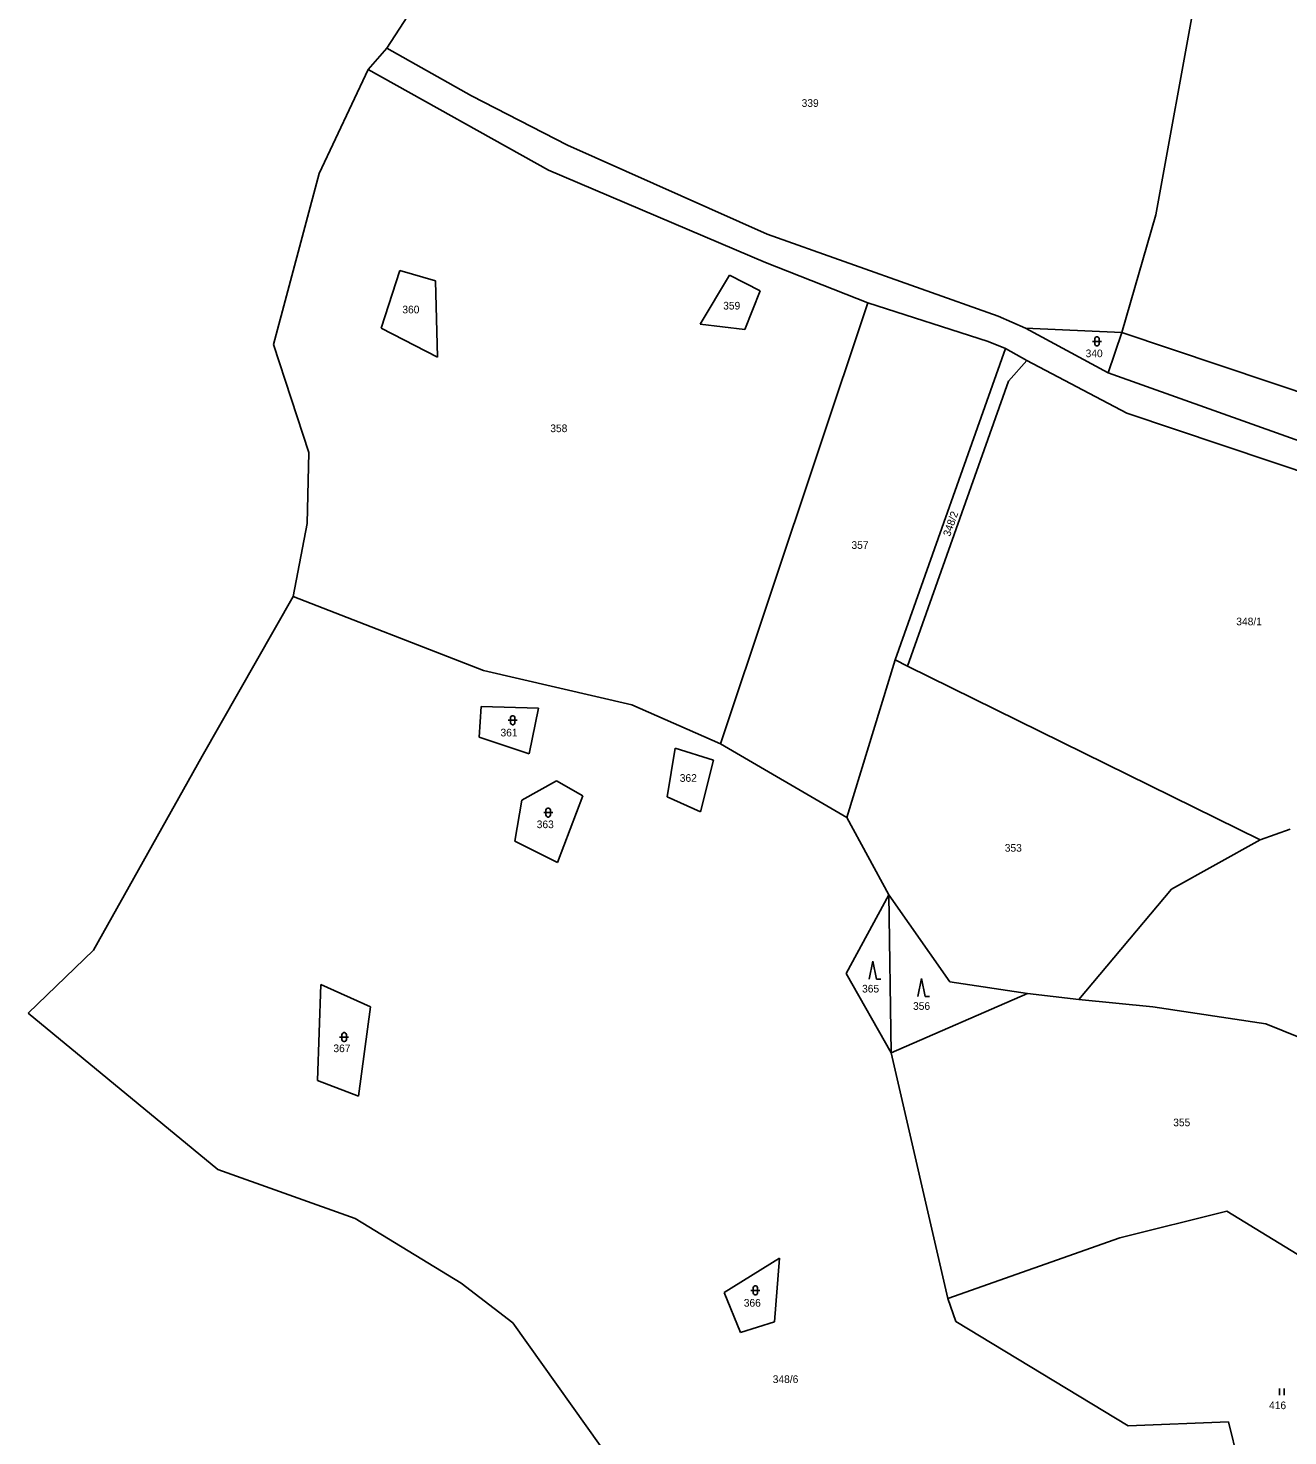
# Model space of a CAD drawing. Extents: x -794421 to -792735, y -1117671 to -1115559.
# Drawn here: x -794420.7 to -794140.7, y -1117103.6 to -1116790.7 of the extents above; entities that cross this region are included whole.
import ezdxf

# ---------------------------------------------------------------- set-up
doc = ezdxf.new("R2010")
doc.units = 0
for name, color, linetype in [('Vrstva 1', 7, 'Continuous'), ('Vrstva 14', 7, 'Continuous'), ('Vrstva 23', 7, 'Continuous'), ('Vrstva 4', 7, 'Continuous')]:
    doc.layers.add(name, color=color, linetype=linetype)

msp = doc.modelspace()

# ---------------------------------------------------------------- linework, layer by layer
at = {"layer": 'Vrstva 1'}
for p, q in [((-794161.02, -1116782.51), (-794170.01, -1116832.22)), ((-794340.93, -1116795.12), (-794322.16, -1116805.77)), ((-794345.11, -1116799.88), (-794305, -1116822.28)), ((-794322.16, -1116805.77), (-794300.83, -1116816.69)), ((-794300.83, -1116816.69), (-794256.39, -1116836.48)), ((-794305, -1116822.28), (-794256.82, -1116842.78)), ((-794170.01, -1116832.22), (-794177.62, -1116858.32)), ((-794256.39, -1116836.48), (-794205.08, -1116854.73)), ((-794342.23, -1116857.41), (-794338.11, -1116844.55)), ((-794338.11, -1116844.55), (-794330.16, -1116846.87)), ((-794256.82, -1116842.78), (-794234.07, -1116851.75)), ((-794330.16, -1116846.87), (-794329.71, -1116863.85)), ((-794271.32, -1116856.49), (-794264.82, -1116845.62)), ((-794264.82, -1116845.62), (-794257.96, -1116849.1)), ((-794257.96, -1116849.1), (-794261.38, -1116857.68)), ((-794266.82, -1116949.75), (-794234.07, -1116851.75)), ((-794234.07, -1116851.75), (-794207.31, -1116860.32)), ((-794205.08, -1116854.73), (-794199.03, -1116857.38)), ((-794329.71, -1116863.85), (-794342.23, -1116857.41)), ((-794261.38, -1116857.68), (-794271.32, -1116856.49)), ((-794199.03, -1116857.38), (-794177.62, -1116858.32)), ((-794180.61, -1116867.3), (-794199.03, -1116857.38)), ((-794207.31, -1116860.32), (-794203.46, -1116861.91)), ((-794177.62, -1116858.32), (-794180.61, -1116867.3)), ((-794177.62, -1116858.32), (-794117.35, -1116878.62)), ((-794203.46, -1116861.91), (-794228, -1116931.14)), ((-794203.46, -1116861.91), (-794198.74, -1116864.57)), ((-794198.74, -1116864.57), (-794202.79, -1116869.2)), ((-794198.74, -1116864.57), (-794176.47, -1116876.29)), ((-794202.79, -1116869.2), (-794225.24, -1116932.5)), ((-794180.61, -1116867.3), (-794121.37, -1116888.44)), ((-794176.47, -1116876.29), (-794087.13, -1116906.27)), ((-794361.8, -1116917.06), (-794319.51, -1116933.5)), ((-794228, -1116931.14), (-794238.71, -1116966.15)), ((-794228, -1116931.14), (-794225.24, -1116932.5)), ((-794225.24, -1116932.5), (-794146.84, -1116971.14)), ((-794319.51, -1116933.5), (-794286.54, -1116941.11)), ((-794320.44, -1116948.27), (-794320.03, -1116941.5)), ((-794320.03, -1116941.5), (-794307.28, -1116941.84)), ((-794307.28, -1116941.84), (-794309.35, -1116952.01)), ((-794286.54, -1116941.11), (-794266.82, -1116949.75)), ((-794309.35, -1116952.01), (-794320.44, -1116948.27)), ((-794278.69, -1116961.59), (-794276.9, -1116950.76)), ((-794276.9, -1116950.76), (-794268.37, -1116953.42)), ((-794238.71, -1116966.15), (-794266.82, -1116949.75)), ((-794268.37, -1116953.42), (-794271.28, -1116964.86)), ((-794310.99, -1116962.29), (-794303.23, -1116957.97)), ((-794303.23, -1116957.97), (-794297.42, -1116961.34)), ((-794312.52, -1116971.45), (-794310.99, -1116962.29)), ((-794297.42, -1116961.34), (-794303.06, -1116976.14)), ((-794271.28, -1116964.86), (-794278.69, -1116961.59)), ((-794238.71, -1116966.15), (-794229.41, -1116983.37)), ((-794146.84, -1116971.14), (-794140.21, -1116968.76)), ((-794303.06, -1116976.14), (-794312.52, -1116971.45)), ((-794166.58, -1116982.11), (-794146.84, -1116971.14)), ((-794187.16, -1117006.64), (-794166.58, -1116982.11)), ((-794238.83, -1117000.84), (-794229.41, -1116983.37)), ((-794229.41, -1116983.37), (-794215.84, -1117002.69)), ((-794229.41, -1116983.37), (-794228.89, -1117018.46)), ((-794228.89, -1117018.46), (-794238.83, -1117000.84)), ((-794355.63, -1117003.25), (-794356.35, -1117024.63)), ((-794355.63, -1117003.25), (-794344.61, -1117008.25)), ((-794215.84, -1117002.69), (-794198.58, -1117005.26)), ((-794198.58, -1117005.26), (-794228.89, -1117018.46)), ((-794187.16, -1117006.64), (-794198.58, -1117005.26)), ((-794187.16, -1117006.64), (-794170.7, -1117008.24)), ((-794344.61, -1117008.25), (-794347.26, -1117028.13)), ((-794170.7, -1117008.24), (-794145.61, -1117012.04)), ((-794145.61, -1117012.04), (-794118.17, -1117023.08)), ((-794228.89, -1117018.46), (-794216.26, -1117073.1)), ((-794347.26, -1117028.13), (-794356.35, -1117024.63)), ((-794178.01, -1117059.58), (-794154.29, -1117053.65)), ((-794154.29, -1117053.65), (-794132.18, -1117067.16)), ((-794216.26, -1117073.1), (-794178.01, -1117059.58)), ((-794266.02, -1117071.76), (-794253.72, -1117064.08)), ((-794253.72, -1117064.08), (-794254.77, -1117078.24)), ((-794262.35, -1117080.65), (-794266.02, -1117071.76)), ((-794214.5, -1117078.17), (-794216.26, -1117073.1)), ((-794254.77, -1117078.24), (-794262.35, -1117080.65)), ((-794176.15, -1117101.34), (-794214.5, -1117078.17)), ((-794153.88, -1117100.48), (-794176.15, -1117101.34)), ((-794151.74, -1117109.25), (-794153.88, -1117100.48))]:
    msp.add_line(p, q, dxfattribs=at)
at = {"layer": 'Vrstva 23'}
for p, q in [((-794184.13, -1116860.32), (-794182.13, -1116860.32)), ((-794183.63, -1116859.72), (-794183.53, -1116859.52)), ((-794183.63, -1116860.92), (-794183.63, -1116859.72)), ((-794183.53, -1116861.12), (-794183.63, -1116860.92)), ((-794183.53, -1116859.52), (-794183.43, -1116859.42)), ((-794183.43, -1116859.42), (-794183.23, -1116859.32)), ((-794183.23, -1116859.32), (-794183.03, -1116859.32)), ((-794183.03, -1116859.32), (-794182.83, -1116859.42)), ((-794182.83, -1116859.42), (-794182.73, -1116859.52)), ((-794182.73, -1116859.52), (-794182.63, -1116859.72)), ((-794182.63, -1116860.92), (-794182.73, -1116861.12)), ((-794182.63, -1116859.72), (-794182.63, -1116860.92)), ((-794183.43, -1116861.22), (-794183.53, -1116861.12)), ((-794183.23, -1116861.32), (-794183.43, -1116861.22)), ((-794183.03, -1116861.32), (-794183.23, -1116861.32)), ((-794182.83, -1116861.22), (-794183.03, -1116861.32)), ((-794182.73, -1116861.12), (-794182.83, -1116861.22)), ((-794313.99, -1116944.54), (-794311.99, -1116944.54)), ((-794313.49, -1116943.94), (-794313.39, -1116943.74)), ((-794313.49, -1116945.14), (-794313.49, -1116943.94)), ((-794313.39, -1116945.34), (-794313.49, -1116945.14)), ((-794313.39, -1116943.74), (-794313.29, -1116943.64)), ((-794313.29, -1116945.44), (-794313.39, -1116945.34)), ((-794313.29, -1116943.64), (-794313.09, -1116943.54)), ((-794313.09, -1116945.54), (-794313.29, -1116945.44)), ((-794313.09, -1116943.54), (-794312.89, -1116943.54)), ((-794312.89, -1116943.54), (-794312.69, -1116943.64)), ((-794312.69, -1116945.44), (-794312.89, -1116945.54)), ((-794312.69, -1116943.64), (-794312.59, -1116943.74)), ((-794312.59, -1116945.34), (-794312.69, -1116945.44)), ((-794312.59, -1116943.74), (-794312.49, -1116943.94)), ((-794312.49, -1116945.14), (-794312.59, -1116945.34)), ((-794312.49, -1116943.94), (-794312.49, -1116945.14)), ((-794312.89, -1116945.54), (-794313.09, -1116945.54)), ((-794305.5, -1116964.25), (-794305.4, -1116964.15)), ((-794305.4, -1116964.15), (-794305.2, -1116964.05)), ((-794305.2, -1116964.05), (-794305, -1116964.05)), ((-794305, -1116964.05), (-794304.8, -1116964.15)), ((-794304.8, -1116964.15), (-794304.7, -1116964.25)), ((-794306.1, -1116965.05), (-794304.1, -1116965.05)), ((-794305.6, -1116964.45), (-794305.5, -1116964.25)), ((-794305.6, -1116965.65), (-794305.6, -1116964.45)), ((-794305.5, -1116965.85), (-794305.6, -1116965.65)), ((-794305.4, -1116965.95), (-794305.5, -1116965.85)), ((-794305.2, -1116966.05), (-794305.4, -1116965.95)), ((-794305, -1116966.05), (-794305.2, -1116966.05)), ((-794304.8, -1116965.95), (-794305, -1116966.05)), ((-794304.7, -1116965.85), (-794304.8, -1116965.95)), ((-794304.7, -1116964.25), (-794304.6, -1116964.45)), ((-794304.6, -1116965.65), (-794304.7, -1116965.85)), ((-794304.6, -1116964.45), (-794304.6, -1116965.65)), ((-794233.76, -1117002.06), (-794232.96, -1116998.06)), ((-794232.96, -1116998.06), (-794232.16, -1117002.06)), ((-794232.16, -1117002.06), (-794231.16, -1117002.06)), ((-794222.92, -1117005.92), (-794222.12, -1117001.92)), ((-794222.12, -1117001.92), (-794221.32, -1117005.92)), ((-794221.32, -1117005.92), (-794220.32, -1117005.92)), ((-794350.95, -1117014.36), (-794350.85, -1117014.16)), ((-794350.85, -1117014.16), (-794350.75, -1117014.06)), ((-794350.75, -1117014.06), (-794350.55, -1117013.96)), ((-794350.55, -1117013.96), (-794350.35, -1117013.96)), ((-794350.35, -1117013.96), (-794350.15, -1117014.06)), ((-794350.15, -1117014.06), (-794350.05, -1117014.16)), ((-794350.05, -1117014.16), (-794349.95, -1117014.36)), ((-794351.45, -1117014.96), (-794349.45, -1117014.96)), ((-794350.95, -1117015.56), (-794350.95, -1117014.36)), ((-794350.85, -1117015.76), (-794350.95, -1117015.56)), ((-794350.75, -1117015.86), (-794350.85, -1117015.76)), ((-794350.55, -1117015.96), (-794350.75, -1117015.86)), ((-794350.35, -1117015.96), (-794350.55, -1117015.96)), ((-794350.15, -1117015.86), (-794350.35, -1117015.96)), ((-794350.05, -1117015.76), (-794350.15, -1117015.86)), ((-794349.95, -1117015.56), (-794350.05, -1117015.76)), ((-794349.95, -1117014.36), (-794349.95, -1117015.56)), ((-794259.54, -1117070.66), (-794259.44, -1117070.46)), ((-794259.44, -1117070.46), (-794259.34, -1117070.36)), ((-794259.34, -1117070.36), (-794259.14, -1117070.26)), ((-794259.14, -1117070.26), (-794258.94, -1117070.26)), ((-794258.94, -1117070.26), (-794258.74, -1117070.36)), ((-794258.74, -1117070.36), (-794258.64, -1117070.46)), ((-794258.64, -1117070.46), (-794258.54, -1117070.66)), ((-794260.04, -1117071.26), (-794258.04, -1117071.26)), ((-794259.54, -1117071.86), (-794259.54, -1117070.66)), ((-794259.44, -1117072.06), (-794259.54, -1117071.86)), ((-794259.34, -1117072.16), (-794259.44, -1117072.06)), ((-794259.14, -1117072.26), (-794259.34, -1117072.16)), ((-794258.94, -1117072.26), (-794259.14, -1117072.26)), ((-794258.74, -1117072.16), (-794258.94, -1117072.26)), ((-794258.64, -1117072.06), (-794258.74, -1117072.16)), ((-794258.54, -1117071.86), (-794258.64, -1117072.06)), ((-794258.54, -1117070.66), (-794258.54, -1117071.86)), ((-794142.54, -1117094.57), (-794142.54, -1117093.07)), ((-794141.54, -1117093.07), (-794141.54, -1117094.57))]:
    msp.add_line(p, q, dxfattribs=at)
at = {"layer": 'Vrstva 4'}
for p, q in [((-794320.91, -1116764.13), (-794340.93, -1116795.12)), ((-794340.93, -1116795.12), (-794345.11, -1116799.88)), ((-794345.11, -1116799.88), (-794356, -1116823.02)), ((-794356, -1116823.02), (-794366.16, -1116860.99)), ((-794366.16, -1116860.99), (-794358.32, -1116885.05)), ((-794358.32, -1116885.05), (-794358.7, -1116900.77)), ((-794358.7, -1116900.77), (-794361.8, -1116917.06)), ((-794361.8, -1116917.06), (-794382.03, -1116952.49)), ((-794382.03, -1116952.49), (-794406.18, -1116995.67)), ((-794406.18, -1116995.67), (-794420.69, -1117009.62)), ((-794420.69, -1117009.62), (-794378.52, -1117044.39)), ((-794378.52, -1117044.39), (-794347.98, -1117055.25)), ((-794347.98, -1117055.25), (-794324.43, -1117069.66)), ((-794324.43, -1117069.66), (-794312.96, -1117078.48)), ((-794312.96, -1117078.48), (-794285.59, -1117116.88))]:
    msp.add_line(p, q, dxfattribs=at)

# ---------------------------------------------------------------- texts
at = {"layer": 'Vrstva 14'}
for s, p in [('339', (-794248.767, -1116808.2)), ('359', (-794266.203, -1116853.24)), ('360', (-794337.516, -1116854.09)), ('340', (-794185.642, -1116863.84)), ('358', (-794304.633, -1116880.5)), ('357', (-794237.69, -1116906.44)), ('348/1', (-794152.149, -1116923.43)), ('361', (-794315.7, -1116948.13)), ('362', (-794275.847, -1116958.22)), ('363', (-794307.647, -1116968.52)), ('353', (-794203.613, -1116973.75)), ('365', (-794235.333, -1117005.05)), ('356', (-794224.003, -1117008.91)), ('367', (-794352.843, -1117018.31)), ('355', (-794166.169, -1117034.78)), ('366', (-794261.627, -1117074.88)), ('348/6', (-794255.186, -1117091.85)), ('416', (-794144.866, -1117097.66))]:
    msp.add_text(s, height=1.7, dxfattribs=at).set_placement(p)
msp.add_text('348/2', height=1.7, rotation=70.83162, dxfattribs=at).set_placement((-794215.788, -1116903.833))

doc.saveas('drawing.dxf')
